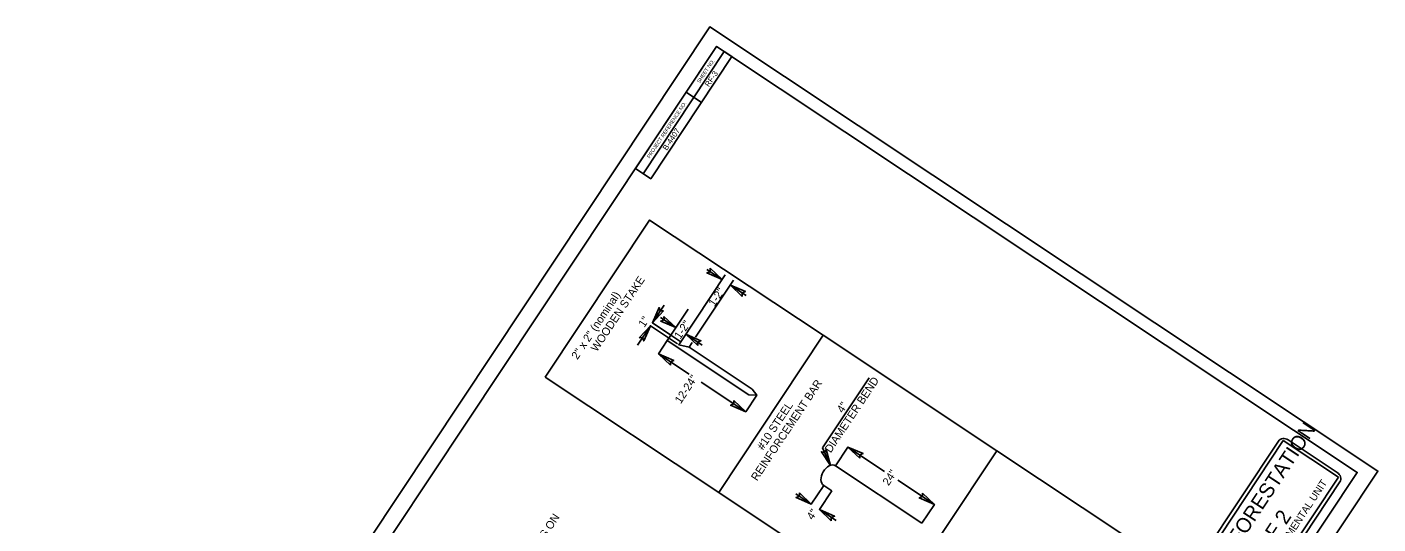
# Model space of a CAD drawing. Extents: x 561231 to 564240, y 590260 to 602519.
# Drawn here: x 563134 to 564240, y 591058 to 591465 of the extents above; entities that cross this region are included whole.
import ezdxf

# ---------------------------------------------------------------- set-up
doc = ezdxf.new("R2010")
doc.units = 0
for name, color, linetype in [('Old_Level_1', 7, 'Continuous'), ('Scratch_Level_0', 7, 'Continuous'), ('Sheet Plot Border Outside CELL', 7, 'Continuous')]:
    doc.layers.add(name, color=color, linetype=linetype)

msp = doc.modelspace()

# ---------------------------------------------------------------- linework, layer by layer
at = {"layer": 'Old_Level_1'}
for p, q in [((563638.4, 591344.5), (563704.9, 591444.5)), ((563673.7, 591411.2), (563686.2, 591402.9)), ((563669.4, 591207), (563705.8, 591261.8)), ((563690.6, 591266.2), (563703.1, 591257.9)), ((563681.5, 591210.7), (563712.5, 591257.3)), ((563722.9, 591244.8), (563709.9, 591253.4)), ((563655.7, 591237), (563646.1, 591222.5)), ((563661.3, 591212.4), (563675.4, 591233.6)), ((563633.9, 591204.2), (563644.4, 591220)), ((563666.7, 591205.2), (563644.4, 591220)), ((563661.3, 591212.4), (563646.1, 591222.5)), ((563647.1, 591218.2), (563647.1, 591218.2)), ((563648.8, 591220.7), (563648.8, 591220.7)), ((563652.8, 591226.8), (563665.3, 591218.5)), ((563680.9, 591224.4), (563680.9, 591224.4)), ((563687.7, 591219.9), (563687.7, 591219.9)), ((563651.1, 591197), (563658.3, 591207.9)), ((563686.8, 591204.2), (563673.4, 591213.1)), ((563675.2, 591215.8), (563675.2, 591215.8)), ((563676.1, 591202.5), (563678.7, 591206.4)), ((563676.2, 591180.3), (563651.1, 591197)), ((563685.9, 591173.9), (563722.5, 591149.6)), ((563785.5, 591120), (563823.5, 591177.3)), ((563731.5, 591163.1), (563722.5, 591149.5)), ((563724.3, 591152.3), (563724.3, 591152.3)), ((563791.9, 591105.7), (563785.5, 591120)), ((563806.2, 591120.7), (563795.9, 591105.4)), ((563804.3, 591118), (563804.3, 591118)), ((563836.1, 591100.8), (563806.2, 591120.7)), ((564021.5, 590918.7), (564158.7, 591125.6)), ((564022.5, 590914.8), (564162.7, 591126.1)), ((564162.7, 591126.1), (564207.9, 591096.1)), ((564166.6, 591126.7), (564206.9, 591100)), ((563866.8, 591058.3), (563795.9, 591105.4)), ((564067.8, 590884.8), (564207.9, 591096.1)), ((563786.4, 591089.3), (563776.2, 591074)), ((563793.1, 591084.9), (563782.8, 591069.6)), ((563786.4, 591089.3), (563793.1, 591084.9)), ((563847, 591093.6), (563877, 591073.6)), ((564071.8, 590885.3), (564209, 591092.2)), ((563763.4, 591082.5), (563776.2, 591074)), ((563877, 591073.6), (563866.8, 591058.3)), ((563774.4, 591071.3), (563774.4, 591071.3)), ((563796.5, 591060.5), (563782.9, 591069.6)), ((563784.7, 591072.3), (563784.7, 591072.3)), ((563875.2, 591070.9), (563875.2, 591070.9))]:
    msp.add_line(p, q, dxfattribs=at)
for points in [[(563698.6, 591448.7), (563200.5, 590699.1), (563725.3, 590350.4), (564223.3, 591100)], [(563632.2, 591348.7), (563698.6, 591448.7), (563711.1, 591440.4), (563644.7, 591340.4)], [(563558.2, 591177.8), (563643.8, 591306.6), (563786, 591212.2), (563700.4, 591083.4)], [(563693.4, 591267.1), (563703.1, 591257.9), (563690.7, 591263.3), (563693.4, 591264.3)], [(563719.7, 591244.1), (563709.9, 591253.4), (563722.3, 591248), (563719.6, 591246.9)], [(563655.3, 591232.3), (563646.1, 591222.5), (563651.5, 591234.9), (563652.5, 591232.2)], [(563655.5, 591227.7), (563665.3, 591218.5), (563652.9, 591223.9), (563655.6, 591224.9)], [(563635.2, 591210.2), (563644.4, 591220), (563639, 591207.6), (563638, 591210.3)], [(563683.2, 591203.9), (563673.4, 591213.1), (563685.8, 591207.7), (563683.1, 591206.7)], [(563700.4, 591083.4), (563786, 591212.2), (563928.1, 591117.7), (563842.5, 590988.9)], [(563660.8, 591187.8), (563651.1, 591197), (563663.5, 591191.6), (563660.8, 591190.6)], [(563712.7, 591158.8), (563722.5, 591149.6), (563710.1, 591155), (563712.8, 591156)], [(563788.5, 591118.6), (563791.9, 591105.7), (563784.5, 591116.8), (563787.2, 591116.2)], [(563815.9, 591111.5), (563806.2, 591120.7), (563818.6, 591115.3), (563815.9, 591114.3)], [(563842.5, 590988.9), (563928.1, 591117.7), (564033, 591048), (563947.4, 590919.2)], [(563766.4, 591083.2), (563776.2, 591074), (563763.8, 591079.4), (563766.5, 591080.5)], [(563867.2, 591082.9), (563877, 591073.6), (563864.6, 591079.1), (563867.3, 591080.1)], [(563792.6, 591060.3), (563782.9, 591069.6), (563795.3, 591064.1), (563792.6, 591063.1)]]:
    msp.add_lwpolyline(points, close=True, dxfattribs=at)
for points in [[(563669.4, 591207), (563661.3, 591212.4), (563658.3, 591207.9), (563725, 591163.6), (563731.5, 591163.1), (563727.9, 591168.1), (563676.1, 591202.5)], [(563669.4, 591207), (563667.7, 591204.5), (563676.1, 591202.5)]]:
    msp.add_lwpolyline(points, dxfattribs=at)
for centre, major_axis, ratio, start_param, end_param in [((564163.7, 591122.2), (-5.03, 3.34), 0.880425, 4.713138, 6.283935), ((563791.2, 591097.4), (-4.77, -8.05), 0.648502, 3.141593, 6.283185), ((564203.9, 591095.5), (-5.03, 3.34), 0.880425, 3.142342, 4.713138)]:
    msp.add_ellipse(centre, major_axis=major_axis, ratio=ratio, start_param=start_param, end_param=end_param, dxfattribs=at)
at = {"layer": 'Scratch_Level_0'}
msp.add_line((563693, 591464.7), (563693, 591464.7), dxfattribs=at)
at = {"layer": 'Sheet Plot Border Outside CELL'}
msp.add_lwpolyline([(563681.2, 590259.7), (564240.2, 591101.1), (563693, 591464.7), (563134, 590623.3)], close=True, dxfattribs=at)

# ---------------------------------------------------------------- texts
at = {"layer": 'Old_Level_1'}
for s, height, rotation, p in [('SHEET NO.', 3, 56.3995, (563684.8, 591418.4)), ('RF-3', 4.5, 56.3995, (563692.4, 591415.2)), ('PROJECT REFERENCE NO.', 3, 56.3995, (563643.9, 591356.9)), ('B-4407', 4.5, 56.3995, (563657.9, 591363.2)), ('WOODEN STAKE', 6.551, 56.3803, (563600.6, 591198.2)), ('1-2"', 6.55, 56.3803, (563696.9, 591235.2)), ('2" x 2" (nominal)', 6.551, 56.3803, (563584.7, 591191.9)), ('1"', 6.55, 56.3803, (563639.5, 591218.2)), ('1-2"', 6.55, 56.3803, (563668.9, 591208.5)), ('12-24"', 6.55, 56.3803, (563669.3, 591155.7)), ('REINFORCEMENT BAR', 6.551, 56.3803, (563731.8, 591092.5)), ('DIAMETER BEND', 6.551, 56.3803, (563792.1, 591115.4)), ('#10 STEEL', 6.55, 56.3803, (563736.7, 591117.7)), ('4"', 6.55, 56.3803, (563802, 591148.1)), ('STREAMBANK REFORESTATION', 12.073, 56.4482, (564050.1, 590924.9)), ('24"', 6.55, 56.3803, (563839.5, 591088.6)), ('N.C.D.O.T. - ROADSIDE ENVIRONMENTAL UNIT', 6.037, 56.4482, (564098.3, 590939.7)), ('ANCHORS ON', 6.55, 56.3993, (563537.6, 591013.9)), ('4"', 6.55, 56.3803, (563777.3, 591060.5)), ('   DETAIL SHEET 2 OF 2', 12.073, 56.4482, (564069.2, 590912.2))]:
    msp.add_text(s, height=height, rotation=rotation, dxfattribs=at).set_placement(p)

doc.saveas('drawing.dxf')
